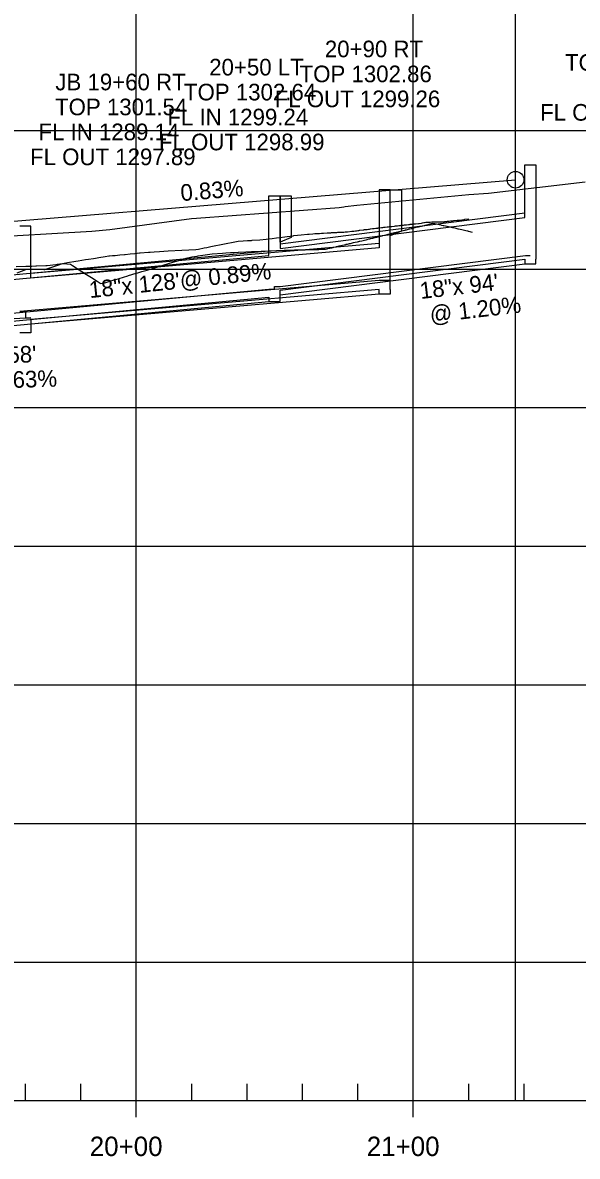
# Model space of a CAD drawing. Extents: x 670877 to 686811, y 705985 to 708501.
# Drawn here: x 685436.3 to 685636.5, y 707872.7 to 708281.7 of the extents above; entities that cross this region are included whole.
import ezdxf

# ---------------------------------------------------------------- set-up
doc = ezdxf.new("R2010")
doc.units = 0
for name, color, linetype in [('30', 7, 'Continuous'), ('37', 7, 'Continuous'), ('DRAINAGE_HGL LEFT', 7, 'Continuous'), ('DRAINAGE_HGL RIGHT', 7, 'Continuous'), ('Profile Drainage Annot Left', 7, 'Continuous'), ('Profile Drainage Annot Right', 7, 'Continuous'), ('R_Drainage Extensions_LEFT', 7, 'Continuous'), ('R_Drainage Extensions_RIGHT', 7, 'Continuous'), ('R_Drainage LEFT', 7, 'Continuous'), ('R_Drainage RIGHT', 7, 'Continuous'), ('R_Exist Surface', 7, 'Continuous'), ('R_No Plot', 7, 'Continuous'), ('R_Profile Work Left', 7, 'Continuous'), ('R_Profile Work Right', 7, 'Continuous'), ('R_Vert Alg', 7, 'Continuous'), ('R_Vert Alg Annot', 7, 'Continuous')]:
    doc.layers.add(name, color=color, linetype=linetype)

msp = doc.modelspace()

# ---------------------------------------------------------------- linework, layer by layer
at = {"layer": '37'}
for p, q in [((685477.28, 707892.85), (685477.28, 708492.85)), ((685577.28, 707892.85), (685577.28, 708492.85)), ((684477.28, 708242.85), (686777.28, 708242.85)), ((684477.28, 708192.85), (686777.28, 708192.85)), ((684477.28, 708142.85), (686777.28, 708142.85)), ((684477.28, 708092.85), (686777.28, 708092.85)), ((684477.28, 708042.85), (686777.28, 708042.85)), ((684477.28, 707992.85), (686777.28, 707992.85)), ((684477.28, 707942.85), (686777.28, 707942.85)), ((685437.28, 707892.85), (685437.28, 707898.85)), ((685457.28, 707892.85), (685457.28, 707898.85)), ((685497.28, 707892.85), (685497.28, 707898.85)), ((685517.28, 707892.85), (685517.28, 707898.85)), ((685537.28, 707892.85), (685537.28, 707898.85)), ((685557.28, 707892.85), (685557.28, 707898.85)), ((685597.28, 707892.85), (685597.28, 707898.85)), ((685617.28, 707892.85), (685617.28, 707898.85)), ((684477.28, 707892.85), (686777.28, 707892.85)), ((685477.28, 707886.85), (685477.28, 707892.85)), ((685577.28, 707886.85), (685577.28, 707892.85))]:
    msp.add_line(p, q, dxfattribs=at)
at = {"layer": 'DRAINAGE_HGL LEFT'}
msp.add_lwpolyline([(684855.2, 708111.48), (684875.01, 708112.97), (684877.28, 708112.97), (684877.28, 708115), (684879.28, 708115), (685124.73, 708147.9), (685126.73, 708147.9), (685126.73, 708147.9), (685128.73, 708147.9), (685230.25, 708157.07), (685232.25, 708157.07), (685232.25, 708158.42), (685234.25, 708158.42), (685525.17, 708185.62), (685527.18, 708185.62), (685527.18, 708186.58), (685529.23, 708186.58), (685617.8, 708197.78), (685619.52, 708197.78)], dxfattribs=at)
at = {"layer": 'DRAINAGE_HGL RIGHT'}
msp.add_lwpolyline([(685566.98, 708188.74), (685568.98, 708188.74), (685568.98, 708188.74), (685565, 708188.74), (685435.23, 708177.54), (685437.24, 708177.54), (685437.24, 708175.27), (685439.26, 708175.27), (685378.95, 708171.67), (685376.97, 708171.67), (685376.97, 708170.59), (685375, 708170.59), (685230.25, 708160.29), (685232.25, 708160.29), (685232.25, 708157.7), (685234.25, 708157.7), (685124.73, 708144.8), (685126.73, 708144.8), (685126.73, 708143.15), (685128.73, 708143.15), (684875.28, 708121.55)], dxfattribs=at)
at = {"layer": 'R_Drainage Extensions_LEFT'}
msp.add_lwpolyline([(685529.18, 708219.25), (685533.18, 708219.25), (685533.18, 708204.25), (685529.18, 708202.58), (685529.18, 708219.25)], dxfattribs=at)
at = {"layer": 'R_Drainage Extensions_RIGHT'}
msp.add_lwpolyline([(685568.98, 708221.45), (685572.98, 708221.45), (685572.98, 708206.45), (685568.98, 708204.78), (685568.98, 708221.45)], dxfattribs=at)
at = {"layer": 'R_Drainage LEFT'}
for points in [[(685617.52, 708211.41), (685617.52, 708230.45)], [(685617.52, 708230.45), (685621.52, 708230.45)], [(685621.52, 708230.45), (685621.52, 708196.45)], [(685525.15, 708197.75), (685525.15, 708219.25)], [(685525.15, 708219.25), (685529.21, 708219.25)], [(685529.21, 708219.25), (685529.21, 708200.25)], [(685529.21, 708201.91), (685617.52, 708213.08)], [(685529.21, 708200.25), (685617.52, 708211.41)], [(685234.25, 708172.21), (685525.15, 708199.41)], [(685234.25, 708170.55), (685525.15, 708197.75)], [(685529.21, 708185.25), (685617.52, 708196.41)], [(685529.21, 708183.58), (685617.52, 708194.75)], [(685617.52, 708196.41), (685617.52, 708194.75)], [(685617.52, 708194.75), (685621.52, 708194.75)], [(685621.52, 708194.75), (685621.52, 708196.45)], [(685529.21, 708181.08), (685529.21, 708185.25)], [(685234.25, 708155.55), (685525.15, 708182.75)], [(685234.25, 708153.88), (685525.15, 708181.08)], [(685525.15, 708182.75), (685525.15, 708181.08)], [(685525.15, 708181.08), (685529.21, 708181.08)]]:
    msp.add_lwpolyline(points, dxfattribs=at)
at = {"layer": 'R_Drainage RIGHT'}
for points in [[(685568.98, 708221.45), (685564.98, 708221.45)], [(685564.98, 708221.45), (685564.98, 708200.45)], [(685568.98, 708185.45), (685568.98, 708221.45)], [(685439.25, 708208.25), (685435.23, 708208.25)], [(685439.25, 708189.6), (685439.25, 708208.25)], [(685564.98, 708202.11), (685439.25, 708191.26)], [(685564.98, 708200.45), (685439.25, 708189.6)], [(685564.98, 708185.45), (685439.25, 708174.6)], [(685564.98, 708183.78), (685564.98, 708185.45)], [(685568.98, 708185.45), (685568.98, 708183.78)], [(685564.98, 708183.78), (685439.25, 708172.93)], [(685568.98, 708183.78), (685564.98, 708183.78)], [(685439.25, 708174.6), (685439.25, 708169.84)], [(685439.25, 708169.84), (685435.23, 708169.84)]]:
    msp.add_lwpolyline(points, dxfattribs=at)
at = {"layer": 'R_Exist Surface'}
msp.add_lwpolyline([(685112.1, 708168.96), (685162.81, 708175.65), (685164.92, 708175.96), (685215.99, 708183.62), (685218.83, 708184.02), (685266.46, 708190.74), (685270.16, 708191.22), (685317.41, 708196.75), (685320.79, 708197.2), (685365.31, 708201.6), (685370, 708201.88), (685416.05, 708203.83), (685419.8, 708204.14), (685461.21, 708206.48), (685467.7, 708207.16), (685497.2, 708211.08), (685499, 708211.2), (685550.57, 708215), (685552.14, 708215.26), (685552.65, 708215.45), (685556.89, 708215.85), (685597.33, 708219.75), (685604.44, 708220.24), (685639.36, 708224.31)], dxfattribs=at)
at = {"layer": 'R_No Plot'}
msp.add_line((685614.19, 707892.85), (685614.19, 708492.85), dxfattribs=at)
at = {"layer": 'R_Profile Work Left'}
msp.add_lwpolyline([(685434.28, 708191.44), (685437.39, 708192.7), (685437.44, 708192.73), (685439.28, 708192.9), (685440.66, 708192.84), (685440.77, 708192.84), (685443.87, 708192.73), (685444.16, 708192.72), (685444.28, 708192.71), (685447.09, 708193.59), (685447.54, 708193.74), (685449.28, 708194.32), (685450.3, 708194.66), (685450.92, 708194.87), (685453.5, 708194.61), (685454.28, 708194.12), (685454.3, 708194.1), (685456.71, 708192.56), (685457.67, 708191.95), (685459.28, 708190.92), (685459.91, 708190.52), (685461.05, 708189.8), (685463.1, 708188.48), (685464.28, 708187.73), (685464.42, 708187.64), (685465.43, 708187.75), (685466.3, 708188.01), (685467.78, 708188.46), (685469.28, 708188.91), (685469.48, 708188.97), (685471.14, 708189.47), (685472.66, 708189.92), (685474.28, 708190.41), (685474.5, 708190.48), (685477.28, 708191.31), (685477.85, 708191.48), (685479.28, 708191.91), (685481.2, 708192.49), (685484.28, 708193.42), (685489.28, 708194.92), (685494.28, 708196.42), (685495.28, 708196.72), (685497.28, 708197.22), (685498.28, 708197.37), (685499.28, 708197.53), (685499.64, 708197.58), (685504.64, 708198.34), (685508.44, 708198.6), (685509.56, 708198.66), (685511.23, 708198.75), (685512.61, 708198.83), (685514.01, 708198.9), (685514.2, 708198.91), (685516.79, 708199.03), (685518.84, 708199.13), (685519.57, 708199.16), (685520.87, 708199.22), (685522.35, 708199.29), (685523.48, 708199.33), (685525.12, 708199.4), (685525.92, 708199.43), (685527.89, 708199.5), (685528.11, 708199.51), (685530.63, 708199.6), (685530.65, 708199.6), (685532.56, 708199.66), (685532.91, 708199.67), (685533.18, 708199.68), (685534.39, 708199.72), (685535.18, 708199.74), (685535.69, 708199.75), (685536.08, 708199.76), (685536.78, 708199.78), (685537.44, 708199.8), (685537.76, 708199.81), (685538.19, 708199.82), (685539.44, 708199.85), (685539.69, 708199.85), (685540.67, 708199.88), (685540.97, 708199.88), (685541.12, 708199.89), (685541.93, 708199.9), (685542.8, 708199.92), (685543.13, 708199.93), (685544.16, 708199.95), (685544.47, 708199.95), (685545.13, 708199.96), (685545.58, 708200), (685546.16, 708200.14), (685546.39, 708200.19), (685547.85, 708200.54), (685548.05, 708200.58), (685548.37, 708200.66), (685548.63, 708200.72), (685549.32, 708200.88), (685549.54, 708200.93), (685549.83, 708201), (685550.5, 708201.16), (685550.86, 708201.24), (685551.22, 708201.33), (685551.29, 708201.34), (685552.76, 708201.69), (685552.91, 708201.72), (685552.95, 708201.73), (685553.08, 708201.76), (685553.5, 708201.86), (685554.23, 708202.03), (685554.59, 708202.11), (685555.29, 708202.28), (685555.38, 708202.3), (685555.7, 708202.37), (685556.26, 708202.5), (685557.17, 708202.71), (685557.5, 708202.79), (685557.67, 708202.82), (685557.8, 708202.86), (685557.93, 708202.89), (685558.64, 708203.05), (685559.6, 708203.27), (685559.7, 708203.29), (685560.11, 708203.4), (685560.22, 708203.42), (685561.26, 708203.68), (685561.58, 708203.76), (685561.84, 708203.83), (685561.89, 708203.84), (685562.44, 708203.98), (685562.62, 708204.02), (685562.92, 708204.1), (685562.94, 708204.11), (685563.05, 708204.13), (685563.96, 708204.36), (685564.07, 708204.39), (685564.51, 708204.5), (685564.57, 708204.51), (685565.01, 708204.62), (685565.97, 708204.86), (685566, 708204.87), (685566.21, 708204.92), (685566.25, 708204.93), (685567.4, 708205.21), (685567.42, 708205.22), (685567.84, 708205.32), (685568.2, 708205.41), (685568.41, 708205.46), (685568.87, 708205.57), (685569.47, 708205.72), (685569.77, 708205.8), (685570.17, 708205.89), (685570.32, 708205.93), (685570.57, 708205.99), (685571.09, 708206.12), (685571.76, 708206.28), (685572.14, 708206.38), (685572.7, 708206.51), (685572.73, 708206.52), (685573.19, 708206.63), (685574.04, 708206.84), (685574.31, 708206.91), (685574.34, 708206.92), (685574.49, 708206.95), (685574.61, 708206.98), (685574.87, 708207.04), (685575.9, 708207.29), (685576.03, 708207.33), (685576.55, 708207.45), (685576.84, 708207.52), (685577.01, 708207.56), (685577.44, 708207.67), (685577.49, 708207.68), (685578.84, 708208.01), (685579.06, 708208.06), (685579.14, 708208.08), (685579.19, 708208.09), (685580.23, 708208.34), (685580.63, 708208.44), (685580.75, 708208.47), (685581.27, 708208.59), (685581.53, 708208.66), (685581.6, 708208.67), (685582.18, 708208.81), (685582.97, 708209), (685583.39, 708209.1), (685583.73, 708209.18), (685583.86, 708209.22), (685584.33, 708209.33), (685584.94, 708209.26), (685585.22, 708209.2), (685585.45, 708209.15), (685585.61, 708209.12), (685586.09, 708209.02), (685586.66, 708208.89), (685586.87, 708208.85), (685587.44, 708208.72), (685588.09, 708208.58), (685588.11, 708208.58), (685588.29, 708208.54), (685588.96, 708208.39), (685589.34, 708208.31), (685589.43, 708208.29), (685589.51, 708208.27), (685590.47, 708208.06), (685590.55, 708208.04), (685590.9, 708207.96), (685591.4, 708207.85), (685591.75, 708207.77), (685592.28, 708207.65), (685592.64, 708207.56), (685592.99, 708207.48), (685593.35, 708207.4), (685593.65, 708207.33), (685594.8, 708207.06), (685595.3, 708206.95), (685596.21, 708206.73), (685596.94, 708206.56), (685597.02, 708206.54), (685597.23, 708206.49), (685598.57, 708206.17)], dxfattribs=at)
at = {"layer": 'R_Profile Work Right'}
msp.add_lwpolyline([(685433.96, 708193.77), (685437.42, 708193.86), (685437.48, 708193.86), (685439.52, 708193.92), (685441.06, 708193.96), (685441.19, 708193.96), (685444.65, 708194.06), (685444.96, 708194.07), (685445.1, 708194.07), (685448.23, 708194.48), (685448.73, 708194.56), (685450.67, 708194.88), (685451.81, 708195.06), (685452.5, 708195.17), (685455.39, 708195.64), (685456.25, 708195.78), (685456.27, 708195.78), (685458.96, 708196.22), (685460.03, 708196.4), (685461.82, 708196.69), (685462.53, 708196.81), (685463.8, 708197.01), (685466.09, 708197.39), (685467.4, 708197.56), (685467.56, 708197.57), (685468.69, 708197.69), (685469.66, 708197.78), (685471.32, 708197.95), (685472.99, 708198.11), (685473.22, 708198.14), (685475.08, 708198.32), (685476.78, 708198.5), (685478.48, 708198.67), (685478.72, 708198.69), (685481.65, 708198.95), (685482.26, 708198.98), (685483.74, 708199.06), (685485.67, 708199.17), (685488.75, 708199.35), (685493.77, 708199.63), (685498.78, 708199.91), (685499.78, 708200.03), (685501.77, 708200.44), (685502.77, 708200.64), (685503.76, 708200.84), (685504.13, 708200.91), (685509.11, 708201.92), (685512.89, 708202.68), (685514.09, 708202.86), (685515.89, 708202.98), (685517.38, 708203.08), (685518.9, 708203.18), (685519.1, 708203.2), (685521.9, 708203.39), (685524.11, 708203.63), (685524.9, 708203.73), (685526.29, 708203.9), (685527.89, 708204.1), (685529.1, 708204.26), (685530.88, 708204.48), (685531.74, 708204.59), (685533.87, 708204.85), (685534.1, 708204.88), (685536.83, 708205.23), (685536.85, 708205.23), (685539.08, 708205.42), (685539.44, 708205.44), (685539.71, 708205.46), (685540.96, 708205.55), (685541.77, 708205.6), (685542.29, 708205.63), (685542.69, 708205.66), (685543.42, 708205.71), (685544.1, 708205.75), (685544.43, 708205.77), (685544.87, 708205.79), (685546.18, 708205.87), (685546.44, 708205.89), (685547.46, 708205.94), (685547.78, 708205.96), (685547.94, 708205.97), (685548.79, 708206.01), (685549.7, 708206.06), (685550.05, 708206.08), (685551.14, 708206.13), (685551.47, 708206.15), (685552.17, 708206.18), (685552.64, 708206.2), (685553.25, 708206.23), (685553.49, 708206.25), (685555.03, 708206.45), (685555.24, 708206.48), (685555.58, 708206.53), (685555.79, 708206.55), (685556.35, 708206.63), (685556.53, 708206.65), (685556.77, 708206.68), (685557.31, 708206.75), (685557.6, 708206.79), (685557.89, 708206.83), (685557.95, 708206.83), (685559.12, 708206.98), (685559.24, 708207), (685559.27, 708207), (685559.37, 708207.01), (685559.71, 708207.06), (685560.29, 708207.13), (685560.57, 708207.16), (685561.12, 708207.23), (685561.19, 708207.24), (685561.44, 708207.27), (685561.88, 708207.33), (685562.59, 708207.41), (685562.85, 708207.44), (685562.98, 708207.46), (685563.09, 708207.47), (685563.19, 708207.48), (685563.74, 708207.55), (685564.48, 708207.64), (685564.56, 708207.65), (685564.88, 708207.69), (685564.96, 708207.7), (685565.76, 708207.79), (685566.01, 708207.82), (685566.21, 708207.84), (685566.25, 708207.85), (685566.67, 708207.9), (685566.81, 708207.91), (685567.04, 708207.94), (685567.06, 708207.94), (685567.14, 708207.95), (685567.84, 708208.03), (685567.92, 708208.04), (685568.26, 708208.08), (685568.3, 708208.09), (685568.64, 708208.13), (685569.37, 708208.22), (685569.39, 708208.22), (685569.55, 708208.24), (685569.58, 708208.24), (685570.46, 708208.34), (685570.48, 708208.35), (685570.8, 708208.38), (685571.06, 708208.41), (685571.23, 708208.43), (685571.58, 708208.47), (685572.03, 708208.52), (685572.26, 708208.55), (685572.56, 708208.58), (685572.68, 708208.59), (685572.87, 708208.62), (685573.26, 708208.66), (685573.77, 708208.71), (685574.06, 708208.75), (685574.48, 708208.79), (685574.5, 708208.79), (685574.85, 708208.83), (685575.5, 708208.9), (685575.7, 708208.92), (685575.73, 708208.93), (685575.85, 708208.94), (685575.94, 708208.95), (685576.13, 708208.97), (685576.92, 708209.05), (685577.02, 708209.06), (685577.41, 708209.1), (685577.64, 708209.12), (685577.76, 708209.14), (685578.09, 708209.17), (685578.13, 708209.17), (685579.16, 708209.28), (685579.33, 708209.29), (685579.39, 708209.3), (685579.43, 708209.3), (685580.23, 708209.42), (685580.54, 708209.49), (685580.64, 708209.51), (685581.04, 708209.6), (685581.24, 708209.64), (685581.31, 708209.65), (685581.76, 708209.75), (685582.37, 708209.77), (685582.69, 708209.78), (685582.95, 708209.79), (685583.05, 708209.79), (685583.42, 708209.8), (685583.92, 708209.81), (685584.14, 708209.81), (685584.33, 708209.81), (685584.46, 708209.82), (685584.86, 708209.82), (685585.33, 708209.83), (685585.5, 708209.83), (685585.98, 708209.84), (685586.52, 708209.84), (685586.54, 708209.84), (685586.69, 708209.85), (685587.26, 708209.85), (685587.58, 708209.85), (685587.65, 708209.85), (685587.71, 708209.85), (685588.54, 708209.92), (685588.62, 708209.93), (685588.92, 708209.96), (685589.35, 708210.01), (685589.66, 708210.05), (685590.28, 708210.12), (685590.69, 708210.17), (685591.09, 708210.22), (685591.51, 708210.27), (685591.85, 708210.31), (685593.15, 708210.46), (685593.72, 708210.52), (685594.74, 708210.64), (685595.54, 708210.73), (685595.63, 708210.74), (685595.86, 708210.77), (685597.32, 708210.93)], dxfattribs=at)
at = {"layer": 'R_Vert Alg'}
msp.add_line((685426.28, 708209.51), (685614.19, 708225.05), dxfattribs=at)
msp.add_circle((685614.19, 708225.05), 3, dxfattribs=at)

# ---------------------------------------------------------------- texts
at = {"layer": '30'}
for s, p in [('20+00', (685460.47, 707872.85)), ('21+00', (685560.47, 707872.85))]:
    msp.add_text(s, height=7, dxfattribs=at).set_placement(p)
at = {"layer": 'Profile Drainage Annot Left'}
for s, p in [('20+50 LT', (685503.6, 708262.67)), ('TOP 1303.76', (685632.05, 708264.36)), ('TOP 1302.64', (685494.49, 708253.67)), ('FL IN 1299.24', (685488.49, 708244.67)), ('FL OUT 1300.36', (685623.05, 708246.36)), ('FL OUT 1298.99', (685485.46, 708235.67))]:
    msp.add_text(s, height=6, dxfattribs=at).set_placement(p)
for s, p in [('18"x 94\'', (685579.98, 708182.02)), ('@ 1.20%', (685583.55, 708173.38))]:
    msp.add_text(s, height=6, rotation=6.603, dxfattribs=at).set_placement(p)
at = {"layer": 'Profile Drainage Annot Right'}
for s, p in [('20+90 RT', (685545.35, 708269.23)), ('JB 19+60 RT', (685448.06, 708257.31)), ('TOP 1302.86', (685536.24, 708260.23)), ('FL OUT 1299.26', (685527.24, 708251.23)), ('TOP 1301.54', (685447.95, 708248.31)), ('FL IN 1289.14', (685441.95, 708239.31)), ('FL OUT 1297.89', (685438.92, 708230.31))]:
    msp.add_text(s, height=6, dxfattribs=at).set_placement(p)
for s, rotation, p in [('18"x 128\'@ 0.89%', 6.0121, (685460.53, 708182.34)), ('18"x 58\'', 1.7647, (685412.83, 708158.33)), ('@ 0.63%', 1.7647, (685415.66, 708149.41))]:
    msp.add_text(s, height=6, rotation=rotation, dxfattribs=at).set_placement(p)
at = {"layer": 'R_Vert Alg Annot'}
msp.add_text('0.83%', height=6, rotation=4.7255, dxfattribs=at).set_placement((685493.47, 708217.32))

doc.saveas('drawing.dxf')
